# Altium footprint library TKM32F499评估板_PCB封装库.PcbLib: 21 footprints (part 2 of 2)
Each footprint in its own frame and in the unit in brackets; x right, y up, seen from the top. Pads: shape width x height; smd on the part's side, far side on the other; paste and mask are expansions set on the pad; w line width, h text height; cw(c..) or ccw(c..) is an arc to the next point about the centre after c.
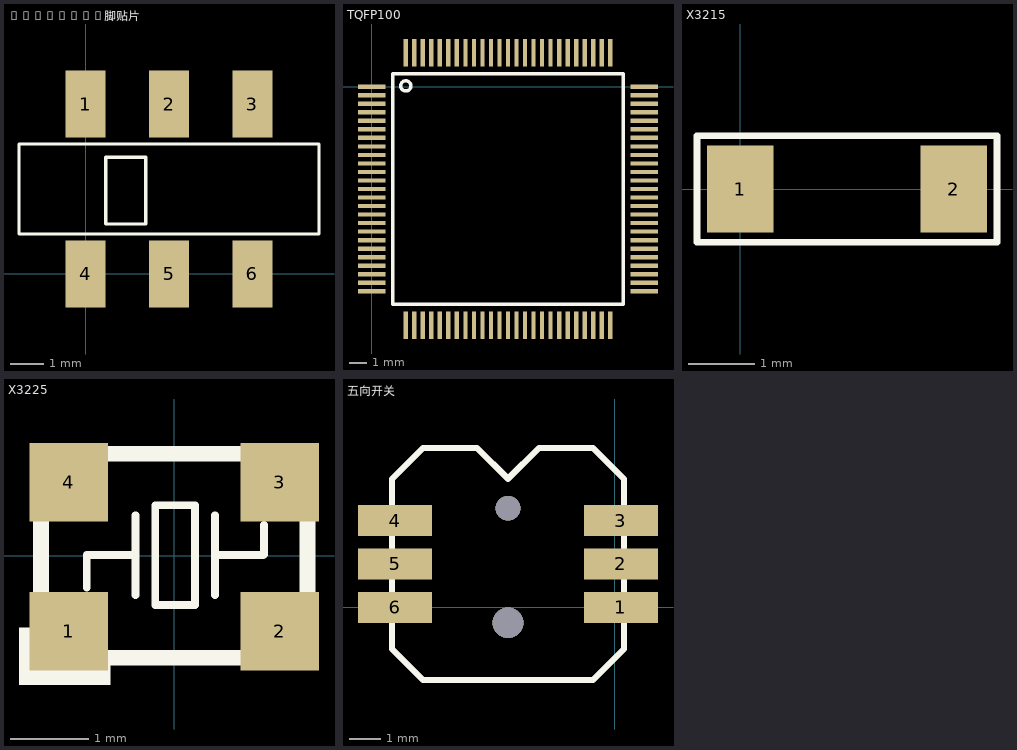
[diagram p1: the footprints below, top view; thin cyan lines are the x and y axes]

## SWITCH_6脚贴片 [mm]
pads (6):
  rect 1.2x2 smd: 1(0,5.1) 2(2.5,5.1) 3(5,5.1) 4(0,0) 5(2.5,0) 6(5,0)
Top Overlay:
  lines w0.1: -2,1.2 7,1.2 7,3.9 -2,3.9 -2,1.2 ; 0.6,1.5 1.8,1.5 1.8,3.5 0.6,3.5 0.6,1.5
3D body: height 5.45, standoff 0, extent -2.05,-0.9 7,6

## TQFP100 [mm]
pads (100):
  rect 1.6x0.25 smd: 1(0,0) 2(0,-0.5) 3(0,-1) 4(0,-1.5) 5(0,-2) 6(0,-2.5) 7(0,-3) 8(0,-3.5) 9(0,-4) 10(0,-4.5) 11(0,-5) 12(0,-5.5) 13(0,-6) 14(0,-6.5) 15(0,-7) 16(0,-7.5) 17(0,-8) 18(0,-8.5) 19(0,-9) 20(0,-9.5) 21(0,-10) 22(0,-10.5) 23(0,-11) 24(0,-11.5) 25(0,-12) 51(16,-12) 52(16,-11.5) 53(16,-11) 54(16,-10.5) 55(16,-10) 56(16,-9.5) 57(16,-9) 58(16,-8.5) 59(16,-8) 60(16,-7.5) 61(16,-7) 62(16,-6.5) 63(16,-6) 64(16,-5.5) 65(16,-5) 66(16,-4.5) 67(16,-4) 68(16,-3.5) 69(16,-3) 70(16,-2.5) 71(16,-2) 72(16,-1.5) 73(16,-1) 74(16,-0.5) 75(16,0)
  rect 0.25x1.6 smd: 26(2,-14) 27(2.5,-14) 28(3,-14) 29(3.5,-14) 30(4,-14) 31(4.5,-14) 32(5,-14) 33(5.5,-14) 34(6,-14) 35(6.5,-14) 36(7,-14) 37(7.5,-14) 38(8,-14) 39(8.5,-14) 40(9,-14) 41(9.5,-14) 42(10,-14) 43(10.5,-14) 44(11,-14) 45(11.5,-14) 46(12,-14) 47(12.5,-14) 48(13,-14) 49(13.5,-14) 50(14,-14) 76(14,2) 77(13.5,2) 78(13,2) 79(12.5,2) 80(12,2) 81(11.5,2) 82(11,2) 83(10.5,2) 84(10,2) 85(9.5,2) 86(9,2) 87(8.5,2) 88(8,2) 89(7.5,2) 90(7,2) 91(6.5,2) 92(6,2) 93(5.5,2) 94(5,2) 95(4.5,2) 96(4,2) 97(3.5,2) 98(3,2) 99(2.5,2) 100(2,2)
Top Overlay:
  circle w0.2: c2,0.05 r0.3
  lines w0.2: 1.25,-12.75 1.25,0.75 14.75,0.75 14.75,-12.75 1.25,-12.75
3D body: height 1.1, standoff 0, extent 0,-14.009 16.017,2.009

## X3215 [mm]
pads (2):
  rect 1x1.3 smd: 1(0,0) 2(3.2,0)
Top Overlay:
  lines w0.1: -0.65,-0.8 -0.65,0.8 3.85,0.8 3.85,-0.8 -0.65,-0.8
3D body: height 0.81, standoff 0, extent 0,-0.762 3.2,0.738

## X3225 [mm]
pads (4):
  rect 1x1 smd: 1(-1.346,-0.965) 2(1.346,-0.965) 3(1.346,0.94) 4(-1.346,0.94)
Top Overlay:
  rectangle: -1.981,-1.651 -1.803,-0.914
  rectangle: -1.803,-1.651 -0.813,-1.397
  lines w0.1: -1.118,-0.406 -1.118,0.008 -0.496,0.008 ; -0.496,-0.5 -0.496,0.516 ; 0.52,-0.5 0.52,0.516 ; 0.52,0.008 1.135,0.008 1.143,0.016 ; 1.143,0.025 1.143,0.39 ; -0.242,-0.627 0.266,-0.627 0.266,-0.309 0.266,0.326 0.266,0.643 -0.242,0.643 -0.242,-0.627
  lines w0.2: -1.7,-1.3 -1.7,1.3 1.7,1.3 1.7,-1.3 -1.7,-1.3
3D body: height 0.72, standoff 0, extent -1.549,-1.281 1.651,1.219

## 五向开关 [mm]
pads (6):
  rect 2.4x1 smd: 1(0.2,0) 2(0.2,1.4) 3(0.2,2.8) 4(-7.1,2.8) 5(-7.1,1.4) 6(-7.1,0)
via -3.45,-0.5 diameter 1 hole 1
via -3.45,3.2 diameter 0.8 hole 0.8
Top Overlay:
  lines w0.2: -7.2,-1.35 -6.2,-2.35 -0.7,-2.35 0.3,-1.35 0.3,4.15 -0.7,5.15 -2.45,5.15 -3.45,4.15 -4.45,5.15 -6.2,5.15 -7.2,4.15 -7.2,-1.35
3D body: height 4.86, standoff -0.4, extent -7.175,-2.375 0.375,5.175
